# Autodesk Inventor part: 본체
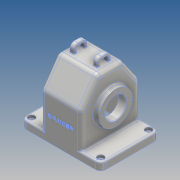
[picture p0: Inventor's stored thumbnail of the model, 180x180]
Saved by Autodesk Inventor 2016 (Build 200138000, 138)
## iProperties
Created: 2016-12
Part Number: 본체
Material: 알루미늄 6061
Document SubType Name: Modeling
Designer: Administrator
Density: 2.7 g/cm^3
Appearance: 알루미늄 - 평지
Mass: 1063.42 g
Surface Area: 1137.96 cm^2
Volume: 393.859 cm^3
Author: Administrator
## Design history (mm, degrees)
sketch "스케치1"
  geometry: L1 (-75, -55)-(75, -55); L2 (75, -55)-(75, 55); L3 (75, 55)-(-75, 55); L4 (-75, 55)-(-75, -55); L5 (-75, -55)-(75, 55); L6 (75, -55)-(-75, 55); 1 further point
  constraints: 12 end point, 2 midpoint, 2 parallel, 1 horizontal, 1 perpendicular
  dimensions: "d0" = 150 distance of L2.end L3.end; "d1" = 110 distance of L1.end L2.end
extrude "돌출1" new body sketch "스케치1" distance "d2" = 15; taper "d3" = 0 deg
sketch "스케치2"
  geometry: L1 (55, 15)-(-55, 15) reference; L2 (-55, 15)-(-55, 80); L3 (-55, 80)-(-23.491, 125); L4 (-23.491, 125)-(23.491, 125); L5 (23.491, 125)-(55, 80); L6 (55, 80)-(55, 15); L7 (0, 0)-(0, 125); L8 (55, 0)-(-55, 0) reference; 1 further point
  constraints: 12 end point, 3 point on line, 2 midpoint, 2 perpendicular, 2 vertical, 1 coincident, 1 vertical alignment, 2 other
  dimensions: "d4" = 125 distance between parallel lines of L4 L8; "d5" = 80 distance from line of L5.end L8; "d6" = 35 deg angle of L2 L3
extrude "돌출2" join sketch "스케치2" stored distance "d7" = 77; taper "d8" = 0 deg
fillet "모깎기1" dims "d9" = 10
node "작업 평면2"
sketch "스케치4"
  geometry: L1 (-18.285, 125)-(18.285, 125) reference; L2 (-12.5, 125)-(-12.5, 140); L3 (-12.5, 140)-(12.5, 140); L4 (12.5, 140)-(12.5, 125); L5 (-7.5, 125)-(-7.5, 135); L6 (-7.5, 135)-(7.5, 135); L7 (7.5, 135)-(7.5, 125); L8 (55, 0)-(-55, 0) reference; 4 further points
  constraints: 12 end point, 4 perpendicular, 4 point on line, 3 midpoint, 2 vertical, 2 vertical alignment
  dimensions: "d18" = 25 distance of L2.end L3.end; "d19" = 15 distance of L5.end L6.end; "d20" = 5 distance between parallel lines of L6 L3; "d21" = 140 distance between parallel lines of L3 L8
extrude "돌출4" join sketch "스케치4" distance "d22" = 8; taper "d23" = 0 deg
fillet "모깎기2" dims "d24" = 8
fillet "모깎기3" dims "d25" = 3
sketch "스케치5"
  geometry: L1 (55, 76.847)-(55, 0) reference; L2 (55, 0)-(-55, 0) reference; L3 (-55, 0)-(-55, 76.847) reference; L4 (-53.192, 82.583)-(-26.477, 120.736) reference; L5 (-18.285, 125)-(18.285, 125) reference; L6 (26.477, 120.736)-(53.192, 82.583) reference; L7 (18.285, 120)-(-18.285, 120); L8 (-22.381, 117.868)-(-49.096, 79.715); L9 (-50, 76.847)-(-50, 0); L10 (50, 0)-(50, 76.847); L11 (49.096, 79.715)-(22.381, 117.868); L12 (55, 0)-(-55, 0) reference; L13 (-50, 0)-(50, 0); A1 r 10 centre (-45, 76.847) between (-53.192, 82.583) and (-55, 76.847) reference; A2 r 10 centre (-18.285, 115) between (-18.285, 125) and (-26.477, 120.736) reference; A3 r 10 centre (18.285, 115) between (26.477, 120.736) and (18.285, 125) reference; A4 r 10 centre (45, 76.847) between (55, 76.847) and (53.192, 82.583) reference; A5 r 5 centre (-18.285, 115) between (-18.285, 120) and (-22.381, 117.868); A6 r 5 centre (-45, 76.847) between (-49.096, 79.715) and (-50, 76.847); A7 r 5 centre (45, 76.847) between (50, 76.847) and (49.096, 79.715); A8 r 5 centre (18.285, 115) between (22.381, 117.868) and (18.285, 120); 1 further point
  constraints: 12 end point, 8 point on circle, 4 centre point, 2 point on line, 1 horizontal, 5 other
  dimensions: "d26" = 5 distance between parallel lines of L5 L7; "d27" = 5 distance between parallel lines of L11 L6; "d28" = 5 distance between parallel lines of L9 L3; "d29" = 5 distance between parallel lines of L1 L10
extrude "돌출5" cut sketch "스케치5" stored distance "d30" = 67; taper "d31" = 0 deg
fillet "모깎기4" dims "d32" = 3
sketch "스케치6"
  geometry: L1 (0, 55)-(0, -55) reference; C1 r 37.5 at (65, 0); 2 further points
  constraints: 1 centre point, 1 horizontal alignment, 1 midpoint
  dimensions: "d33" = 75 diameter of C1; "d34" = 65 distance from line of C1.centre L1
extrude "돌출6" join sketch "스케치6" distance "d35" = 5; taper "d36" = 0 deg
sketch "스케치7"
  geometry: L1 (0, -55)-(0, 55) reference; C1 r 31 at (-65, 0); 2 further points
  constraints: 1 centre point, 1 horizontal alignment, 1 midpoint
  dimensions: "d37" = 62 diameter of C1; "d38" = 65 distance from line of C1.centre L1
extrude "돌출7" join sketch "스케치7" distance "d39" = 10; taper "d40" = 0 deg
sketch "스케치8"
  geometry: L1 (43.5, 27.5)-(43.5, 102.5) reference; L2 (-48.5, 96)-(-48.5, 34) reference; L3 (43.5, 65)-(-48.5, 65); L4 (33.5, 116.147)-(33.5, 77.994) reference; L5 (33.5, 106)-(19.5, 92); L6 (19.5, 92)-(19.5, 65); L7 (33.5, 106)-(33.5, 65); 1 further point
  constraints: 8 end point, 3 point on line, 2 midpoint, 2 perpendicular
  dimensions: "d41" = 45 deg angle of L5 L6; "d42" = 54 diameter of L5.end L3; "d43" = 24 distance between parallel lines of L1 L6
revolve "회전1" sketch "스케치8" stored, may be unused: angle "d44" = 90 deg
hole "구멍1" diameter "d47" = 40; stored, may be unused: countersink angle "d51" = 90 deg, drill point angle "d53" = 0 deg; dims "d45" = 10, "d46" = 10, "d48" = 6, "d49" = 4, "d50" = 2, "d52" = 8
sketch "스케치9"
  geometry: C1 r 20 at (0, 0) reference; 5 further points
  constraints: 1 horizontal alignment, 5 other
  dimensions: "d54" = 26 distance of point (-26, 0) C1.centre; "d57" = 360 deg dimension on C1.centre point (-26, 0) (derived)
hole "구멍2" sketch "스케치9" at (-26, 0), (0, -26), (26, 0), (0, 26) diameter "d59" = 2.459; stored, may be unused: countersink angle "d63" = 90 deg, drill point angle "d65" = 118 deg; dims "d60" = 6, "d61" = 4, "d62" = 2, "d64" = 8
sketch "스케치10"
  geometry: C1 r 20 at (0, 0) reference; C2 r 37.5 at (0, 0) reference; 5 further points
  constraints: 1 horizontal alignment, 5 other
  dimensions: "d66" = 29 distance of point (29, 0) C1.centre; "d69" = 360 deg dimension on C1.centre point (29, 0) (derived)
hole "구멍3" sketch "스케치10" at (29, 0), (0, 29), (-29, 0), (0, -29) diameter "d71" = 2.459; stored, may be unused: countersink angle "d75" = 90 deg, drill point angle "d77" = 118 deg; dims "d72" = 6, "d73" = 4, "d74" = 2, "d76" = 8
fillet "모깎기5" dims "d78" = 10
sketch "스케치11"
  geometry: A1 r 10 centre (65, 45) between (75, 45) and (65, 55) reference; A2 r 10 centre (65, -45) between (65, -55) and (75, -45) reference; A3 r 10 centre (-65, 45) between (-65, 55) and (-75, 45) reference; A4 r 10 centre (-65, -45) between (-75, -45) and (-65, -55) reference; 5 further points
  constraints: 4 coincident
hole "구멍4" sketch "스케치11" at (-65, 45), (-65, -45), (65, -45), (65, 45) diameter "d79" = 5; stored, may be unused: countersink angle "d83" = 90 deg, drill point angle "d85" = 0 deg; dims "d80" = 6, "d81" = 12, "d82" = 5, "d84" = 8
fillet "모깎기6" dims "d86" = 3
sketch "스케치12" dims "d9" = 10
  geometry: L1 (-34.5, -76.847)-(95.5, -76.847) reference; 3 further points
  constraints: 1 midpoint, 1 vertical alignment, 1 other
  dimensions: "d87" = 45 distance from line of point (30.5, -31.847) L1
feature "엠보싱1" sketch "스케치12" dims "d0" = 150, "d1" = 110, "d9" = 10, "d88" = 0.5, "d89" = 0
fillet "모깎기7" dims "d90" = 1
chamfer "모따기1" distance "d91" = 1; stored, may be unused: second distance "d92" = 2, angle "d93" = 45 deg
node "솔리드1"
mirror "대칭1"
node "절단 모서리 투영1"
other parameters: "d17" = 18
